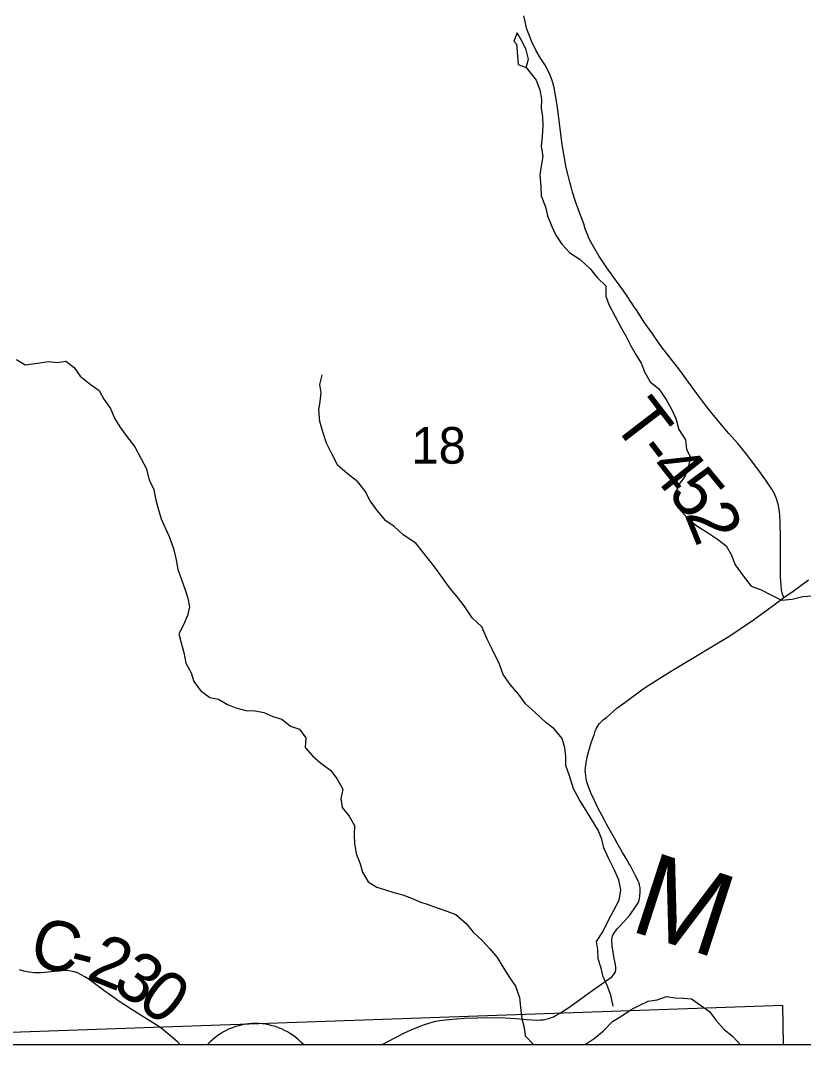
# Model space of a CAD drawing. Extents: x -7.5 to 53.5, y 0 to 22.
# Drawn here: x 4.748 to 5.643, y 14.1 to 15.27 of the extents above; entities that cross this region are included whole.
import ezdxf

# ---------------------------------------------------------------- set-up
doc = ezdxf.new("R2010")
doc.units = 0
for name, color, linetype in [('GM_X_Corporation', 7, 'Continuous'), ('GM_X_County_Road', 7, 'Continuous'), ('GM_X_County_Road_Text', 7, 'Continuous'), ('GM_X_Major_River', 7, 'Continuous'), ('GM_X_Major_River_Text', 7, 'Continuous'), ('GM_X_Minor_Lake', 7, 'Continuous'), ('GM_X_Minor_River', 7, 'Continuous'), ('GM_X_Section_Text', 7, 'Continuous'), ('GM_X_Township_Road', 7, 'Continuous'), ('GM_X_Township_Road_Text', 7, 'Continuous'), ('SH_Data', 7, 'Continuous')]:
    doc.layers.add(name, color=color, linetype=linetype)

msp = doc.modelspace()

# ---------------------------------------------------------------- linework, layer by layer
at = {"layer": 'GM_X_Corporation'}
msp.add_line((4.9619, 14.1), (5.0713, 14.1), dxfattribs=at)
msp.add_lwpolyline([(4.6021, 15.6139), (4.6087, 14.5302), (4.6147, 14.1199), (4.6149, 14.11), (4.6151, 14.1), (8.9, 14.1), (8.9, 19.1887)], dxfattribs=at)
msp.add_lwpolyline([(4.6172, 14.1), (5.6196, 14.1), (5.619, 14.1446), (4.6171, 14.1096)], close=True, dxfattribs=at)
msp.add_arc((5.0166, 14.0496), 0.0744, 42.6893, 137.3107, dxfattribs=at)
at = {"layer": 'GM_X_County_Road'}
for points in [[(4.9084, 14.1189), (4.9021, 14.1232), (4.8953, 14.1273), (4.8849, 14.1338), (4.8747, 14.1403), (4.8672, 14.1452), (4.8621, 14.1485), (4.8564, 14.1526), (4.8435, 14.1619), (4.8342, 14.1686), (4.8266, 14.1742), (4.8218, 14.1774), (4.8175, 14.1798), (4.8132, 14.1819), (4.8094, 14.183), (4.8056, 14.1839), (4.8012, 14.1844), (4.7961, 14.1846), (4.7905, 14.184), (4.78, 14.1827), (4.7716, 14.1819), (4.7643, 14.182), (4.7578, 14.1827), (4.7522, 14.1837), (4.747, 14.1852)], [(4.9306, 14.1), (4.9274, 14.1029), (4.918, 14.1111), (4.9084, 14.1189)]]:
    msp.add_lwpolyline(points, dxfattribs=at)
at = {"layer": 'GM_X_Major_River'}
msp.add_lwpolyline([(5.3931, 14.1), (5.4036, 14.107), (5.4141, 14.1155), (5.4246, 14.1262), (5.4352, 14.1327), (5.4457, 14.14), (5.4555, 14.145), (5.4653, 14.1497), (5.4755, 14.1509), (5.4861, 14.1548), (5.4956, 14.1533), (5.5051, 14.153), (5.5146, 14.1523), (5.5249, 14.1448), (5.5351, 14.1377), (5.5428, 14.1275), (5.5516, 14.1177), (5.5619, 14.1091), (5.5701, 14.1)], dxfattribs=at)
at = {"layer": 'GM_X_Minor_Lake'}
for points in [[(5.326, 15.2164), (5.3286, 15.226), (5.3259, 15.2366), (5.3212, 15.2464), (5.3154, 15.2562), (5.3117, 15.2467), (5.3148, 15.2433)], [(5.3148, 15.2433), (5.3152, 15.2391), (5.3161, 15.2296), (5.3165, 15.2198), (5.326, 15.2164)]]:
    msp.add_lwpolyline(points, dxfattribs=at)
at = {"layer": 'GM_X_Minor_River'}
for points in [[(5.326, 15.2164), (5.3372, 15.2021), (5.3414, 15.1912), (5.3434, 15.1805), (5.3431, 15.1699), (5.3444, 15.1601), (5.3448, 15.1498), (5.3442, 15.1381), (5.3431, 15.1263), (5.3448, 15.1153), (5.343, 15.1039), (5.3415, 15.094), (5.3424, 15.0811), (5.3429, 15.0698), (5.3479, 15.0573), (5.3503, 15.0471), (5.355, 15.035), (5.3596, 15.0251), (5.3665, 15.0146), (5.3757, 15.0048), (5.3875, 14.9973), (5.399, 14.9864), (5.4074, 14.9762), (5.417, 14.9672), (5.4167, 14.9554), (5.4202, 14.9456), (5.4275, 14.932), (5.4345, 14.9192), (5.4402, 14.909), (5.4452, 14.8984), (5.451, 14.8886), (5.4572, 14.8788), (5.4614, 14.8678), (5.4676, 14.8572), (5.4775, 14.8493), (5.4856, 14.8373), (5.4921, 14.8252), (5.4968, 14.8154), (5.5003, 14.8029), (5.508, 14.7912), (5.5088, 14.7805), (5.5135, 14.7707), (5.5109, 14.7597), (5.5076, 14.7498), (5.5005, 14.7403), (5.496, 14.73), (5.4954, 14.7197), (5.503, 14.7096), (5.5122, 14.6994), (5.5218, 14.6919), (5.5328, 14.6851), (5.5443, 14.6777), (5.5542, 14.6698), (5.56, 14.66), (5.5646, 14.6482), (5.5738, 14.6358), (5.583, 14.6237), (5.5944, 14.6196), (5.6051, 14.614), (5.6173, 14.6077), (5.6298, 14.6089), (5.6419, 14.6121), (5.6525, 14.6129)], [(4.7437, 14.883), (4.7536, 14.8767), (4.7679, 14.8787), (4.7797, 14.8807), (4.7903, 14.8796), (4.8001, 14.8808), (4.8097, 14.8737), (4.8162, 14.8639), (4.8277, 14.8545), (4.8379, 14.8474), (4.8433, 14.8376), (4.851, 14.827), (4.8557, 14.8157), (4.8618, 14.8059), (4.8695, 14.7949), (4.8787, 14.7829), (4.886, 14.7693), (4.8918, 14.7587), (4.8953, 14.7454), (4.9004, 14.7341), (4.9023, 14.7239), (4.9051, 14.7137), (4.909, 14.7008), (4.9133, 14.6906), (4.9179, 14.6804), (4.9229, 14.6668), (4.9261, 14.6539), (4.9281, 14.6429), (4.932, 14.6316), (4.9363, 14.6198), (4.9394, 14.61), (4.9414, 14.6002), (4.9388, 14.5903), (4.9347, 14.5804), (4.9291, 14.5693), (4.9319, 14.5591), (4.9346, 14.5481), (4.937, 14.536), (4.9432, 14.5247), (4.9463, 14.5148), (4.954, 14.5047), (4.9643, 14.4964), (4.9742, 14.4946), (4.9848, 14.4886), (4.9943, 14.4849), (5.0057, 14.4816), (5.0163, 14.4813), (5.0262, 14.4795), (5.0365, 14.475), (5.0467, 14.472), (5.0567, 14.4638)], [(5.4253, 14.1438), (5.4224, 14.1565), (5.4182, 14.1675), (5.4139, 14.1773), (5.4116, 14.1871), (5.408, 14.1981), (5.4076, 14.2084), (5.4063, 14.2178), (5.4134, 14.2289), (5.4198, 14.2422), (5.425, 14.2521), (5.4321, 14.2651), (5.4339, 14.2769), (5.4315, 14.2882), (5.4264, 14.2999), (5.4199, 14.3128), (5.4145, 14.3249), (5.4121, 14.3347), (5.4082, 14.3449), (5.4009, 14.3566), (5.3936, 14.3687), (5.3867, 14.3797), (5.3798, 14.3921), (5.3755, 14.4069), (5.3712, 14.419), (5.3711, 14.4292), (5.3699, 14.4391), (5.3671, 14.4497), (5.3579, 14.4606), (5.3484, 14.4681), (5.3358, 14.4798), (5.3251, 14.4895), (5.3174, 14.5001), (5.3074, 14.5114), (5.2994, 14.5227), (5.2955, 14.5348), (5.287, 14.5518), (5.2812, 14.5632), (5.275, 14.5775), (5.2643, 14.5877), (5.2551, 14.6013), (5.2474, 14.6114), (5.239, 14.6212), (5.2213, 14.6454), (5.1999, 14.6729), (5.1854, 14.6826), (5.1751, 14.692), (5.1655, 14.6984), (5.1556, 14.7101), (5.1475, 14.7214), (5.1421, 14.7323), (5.1337, 14.7429), (5.1211, 14.753), (5.1108, 14.7617), (5.1038, 14.7749), (5.0977, 14.7874), (5.0934, 14.8002), (5.0902, 14.812), (5.089, 14.8252), (5.0904, 14.8347), (5.0915, 14.845), (5.0902, 14.8544), (5.0928, 14.8651), (5.0924, 14.8651)], [(5.0567, 14.4638), (5.0669, 14.4605), (5.0742, 14.4506), (5.0732, 14.4396), (5.0816, 14.4298), (5.0911, 14.4216), (5.1022, 14.4137), (5.1095, 14.4039), (5.1164, 14.3918), (5.1142, 14.3808), (5.1155, 14.3709), (5.1235, 14.3611), (5.1297, 14.3502), (5.1294, 14.3396), (5.1299, 14.3297), (5.1315, 14.3183), (5.1361, 14.3066), (5.1389, 14.2968), (5.1454, 14.2858), (5.1553, 14.2798), (5.1652, 14.2769), (5.1747, 14.2736), (5.185, 14.271), (5.1948, 14.2673), (5.2044, 14.2632), (5.2139, 14.2599), (5.2241, 14.2561), (5.2351, 14.2524), (5.2454, 14.2484), (5.2573, 14.2382), (5.2653, 14.2284), (5.2756, 14.219), (5.2844, 14.2092), (5.2925, 14.1994), (5.299, 14.1889), (5.3059, 14.1779), (5.3136, 14.1666), (5.3183, 14.1537), (5.3195, 14.1427), (5.3208, 14.1295), (5.3235, 14.1193), (5.3247, 14.1098), (5.3343, 14.1)]]:
    msp.add_lwpolyline(points, dxfattribs=at)
at = {"layer": 'GM_X_Township_Road'}
for points in [[(5.6203, 14.6107), (5.6188, 14.6147), (5.6176, 14.6195), (5.617, 14.6248), (5.6165, 14.6341), (5.6162, 14.6527), (5.6165, 14.6807), (5.6161, 14.6962), (5.6155, 14.7055), (5.6149, 14.7117), (5.6137, 14.7177), (5.6119, 14.7236), (5.6094, 14.7293), (5.6064, 14.7347), (5.5996, 14.7451), (5.5906, 14.7577), (5.5774, 14.7748), (5.5675, 14.7868), (5.5572, 14.7984), (5.5451, 14.8126), (5.5334, 14.8271), (5.5297, 14.832), (5.5205, 14.8445), (5.5003, 14.872), (5.4889, 14.8867), (5.4794, 14.899), (5.4704, 14.9117), (5.4615, 14.9245), (5.4514, 14.9398), (5.4496, 14.9424), (5.4464, 14.9471), (5.4446, 14.9499), (5.4407, 14.9559), (5.4349, 14.964), (5.429, 14.9722), (5.4181, 14.9877), (5.4089, 15.0013), (5.4032, 15.0111), (5.3982, 15.0201), (5.3966, 15.0234), (5.3961, 15.0248), (5.3946, 15.0282), (5.3932, 15.0321), (5.3915, 15.0377), (5.3878, 15.0478), (5.3825, 15.0624), (5.3788, 15.0742), (5.3772, 15.0802), (5.3757, 15.0854), (5.3734, 15.0946), (5.3713, 15.1043), (5.367, 15.1284), (5.3639, 15.1527), (5.3619, 15.1681), (5.3604, 15.178), (5.3591, 15.1869), (5.3574, 15.1953), (5.3556, 15.2017), (5.3533, 15.2077), (5.351, 15.2128), (5.3474, 15.2192), (5.3423, 15.2273), (5.3373, 15.2355), (5.3323, 15.2459), (5.3288, 15.2547), (5.3263, 15.2616), (5.3245, 15.2693), (5.3232, 15.2756)], [(5.6203, 14.6107), (5.6308, 14.6181), (5.6484, 14.6309)], [(5.3589, 14.1326), (5.3598, 14.1331), (5.3652, 14.1361), (5.3756, 14.1431), (5.3882, 14.1521), (5.4007, 14.1613), (5.4083, 14.1667), (5.416, 14.1719), (5.4235, 14.1775), (5.4257, 14.1797), (5.4274, 14.1822), (5.4281, 14.1848), (5.4282, 14.1879), (5.4278, 14.1916), (5.4264, 14.1982), (5.4241, 14.2126), (5.4237, 14.2191), (5.4244, 14.2241), (5.4266, 14.2282), (5.43, 14.2327), (5.4379, 14.2407), (5.444, 14.2474), (5.4486, 14.2539), (5.4524, 14.2596), (5.454, 14.2628), (5.4547, 14.2649), (5.4553, 14.2669), (5.4557, 14.2697), (5.4561, 14.2746), (5.4559, 14.279), (5.4554, 14.2821), (5.4551, 14.2835), (5.4544, 14.2853), (5.4538, 14.2868), (5.4519, 14.2908), (5.4505, 14.2936), (5.4488, 14.2967), (5.4477, 14.299), (5.4458, 14.3026), (5.4446, 14.3048), (5.4432, 14.307), (5.4419, 14.3094), (5.4389, 14.3144), (5.4359, 14.3196), (5.4329, 14.3249), (5.4298, 14.3302), (5.4266, 14.3357), (5.4235, 14.3411), (5.4205, 14.3465), (5.4176, 14.3518), (5.4148, 14.357), (5.4121, 14.3622), (5.4082, 14.3698), (5.4033, 14.3798), (5.3997, 14.3876), (5.3966, 14.3958), (5.3949, 14.4015), (5.3938, 14.4073), (5.3935, 14.4103), (5.3933, 14.4132), (5.3935, 14.4163), (5.3942, 14.4223), (5.3954, 14.4283), (5.3977, 14.4372), (5.4006, 14.4461), (5.4027, 14.452), (5.4037, 14.4549), (5.4047, 14.4582), (5.4062, 14.4615), (5.4073, 14.4636), (5.4093, 14.4664), (5.4112, 14.4684), (5.4139, 14.471), (5.4174, 14.4739), (5.4294, 14.4842), (5.4384, 14.4909), (5.4445, 14.4953), (5.4519, 14.5008), (5.4594, 14.5063), (5.4671, 14.5115), (5.4907, 14.5264), (5.5173, 14.5424), (5.5414, 14.5566), (5.5572, 14.5664), (5.5702, 14.5749), (5.5855, 14.5855), (5.598, 14.5946), (5.6105, 14.6038), (5.6203, 14.6107)], [(5.1943, 14.1168), (5.1952, 14.1172), (5.2039, 14.1206), (5.2096, 14.1228), (5.2135, 14.1241), (5.2183, 14.1256), (5.2226, 14.1267), (5.2272, 14.1276), (5.2335, 14.1284), (5.2551, 14.13), (5.2707, 14.1306), (5.2893, 14.1308), (5.3017, 14.1306), (5.3141, 14.1299), (5.3265, 14.1287), (5.3327, 14.1281), (5.3389, 14.1279), (5.342, 14.1281), (5.3451, 14.1284), (5.3482, 14.129), (5.3512, 14.1297), (5.357, 14.1318), (5.3589, 14.1326)], [(5.1612, 14.1), (5.162, 14.1004), (5.1757, 14.1078), (5.1867, 14.1134), (5.1943, 14.1168)]]:
    msp.add_lwpolyline(points, dxfattribs=at)
at = {"layer": 'SH_Data'}
msp.add_line((2.1, 14.1), (8.9, 14.1), dxfattribs=at)

# ---------------------------------------------------------------- texts
at = {"layer": 'GM_X_County_Road_Text'}
for s, rotation, p in [('C', 346.5863, (4.7564, 14.1917)), ('2', 338.3268, (4.8218, 14.1759)), ('-', 345.6551, (4.8012, 14.181)), ('3', 325.8408, (4.8511, 14.1646)), ('0', 322.7517, (4.8792, 14.1456))]:
    msp.add_text(s, height=0.0568, rotation=rotation, dxfattribs=at).set_placement(p)
at = {"layer": 'GM_X_Major_River_Text'}
msp.add_text('M', height=0.0947, rotation=342.0549, dxfattribs=at).set_placement((5.442, 14.2308))
at = {"layer": 'GM_X_Section_Text'}
msp.add_text('18', height=0.04186, rotation=0, dxfattribs=at).set_placement((5.1947, 14.7638))
at = {"layer": 'GM_X_Township_Road_Text'}
for s, rotation, p in [('T', 307.5487, (5.423, 14.8107)), ('-', 307.6525, (5.449, 14.7769)), ('4', 308.3401, (5.4637, 14.7579)), ('5', 309.4902, (5.4862, 14.7295)), ('2', 292.1271, (5.5061, 14.7064))]:
    msp.add_text(s, height=0.0568, rotation=rotation, dxfattribs=at).set_placement(p)

doc.saveas('drawing.dxf')
